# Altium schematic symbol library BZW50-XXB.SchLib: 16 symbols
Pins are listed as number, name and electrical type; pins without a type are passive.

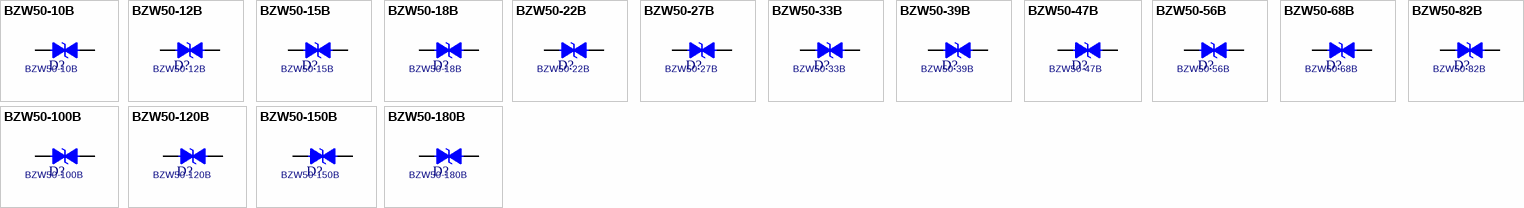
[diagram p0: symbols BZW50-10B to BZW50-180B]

## BZW50-10B
designator D?
footprint ST_R6B
pins: 1, 2

## BZW50-12B
designator D?
footprint ST_R6B
pins: 1, 2

## BZW50-15B
designator D?
footprint ST_R6B
pins: 1, 2

## BZW50-18B
designator D?
footprint ST_R6B
pins: 1, 2

## BZW50-22B
designator D?
footprint ST_R6B
pins: 1, 2

## BZW50-27B
designator D?
footprint ST_R6B
pins: 1, 2

## BZW50-33B
designator D?
footprint ST_R6B
pins: 1, 2

## BZW50-39B
designator D?
footprint ST_R6B
pins: 1, 2

## BZW50-47B
designator D?
footprint ST_R6B
pins: 1, 2

## BZW50-56B
designator D?
footprint ST_R6B
pins: 1, 2

## BZW50-68B
designator D?
footprint ST_R6B
pins: 1, 2

## BZW50-82B
designator D?
footprint ST_R6B
pins: 1, 2

## BZW50-100B
designator D?
footprint ST_R6B
pins: 1, 2

## BZW50-120B
designator D?
footprint ST_R6B
pins: 1, 2

## BZW50-150B
designator D?
footprint st_r6b
pins: 1, 2

## BZW50-180B
designator D?
footprint ST_R6B
pins: 1, 2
